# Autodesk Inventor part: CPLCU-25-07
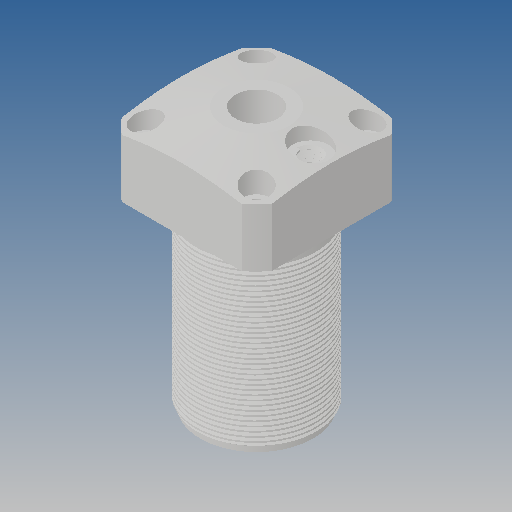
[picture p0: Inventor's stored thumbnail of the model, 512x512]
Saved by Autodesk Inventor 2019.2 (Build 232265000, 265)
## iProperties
Created: 2010-03
Part Number: CPLCU-25-07
Material: Ogólny
Document SubType Name: Modeling
Designer: CADENGINEERING4
Density: 1 g/cm^3
Appearance: Domyślna
Author: CADENGINEERING4
Revision Number: 1LAST_VERSION
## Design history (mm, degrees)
feature "Baza1"
node "Bryła1"
